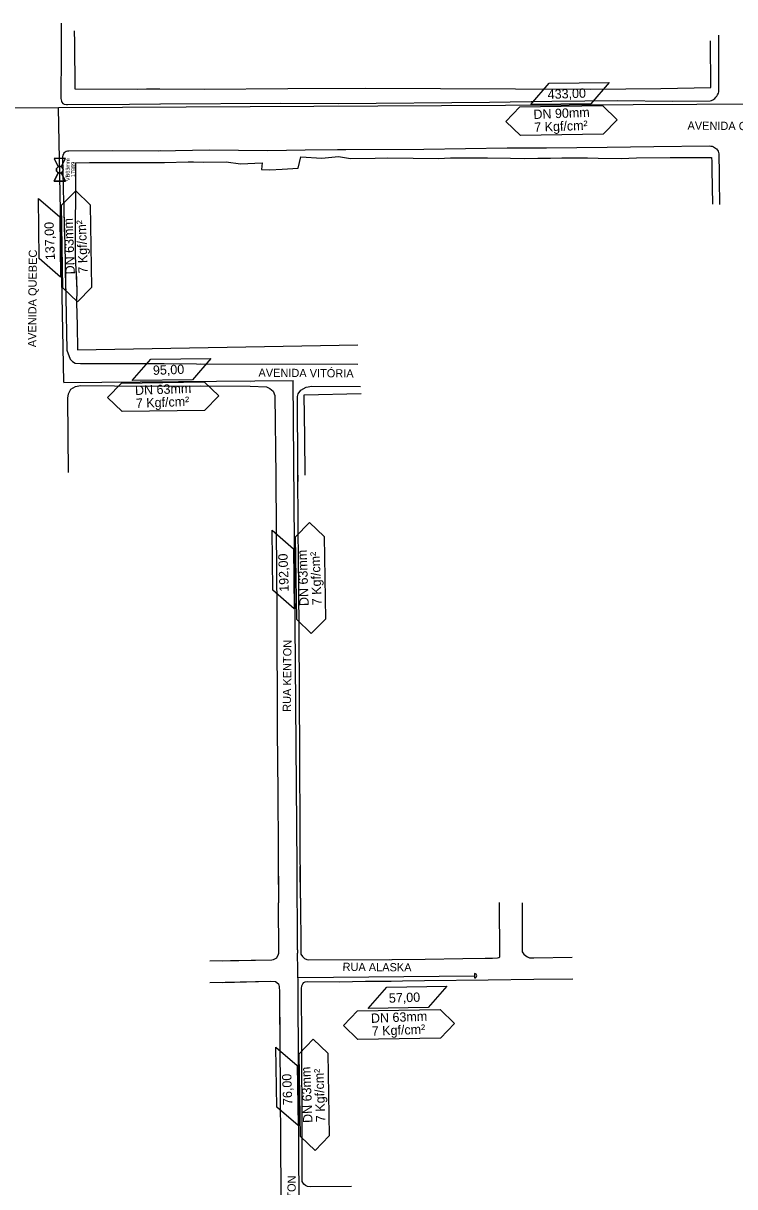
# Model space of a CAD drawing. Extents: x 325899 to 364828, y 7568995 to 7592502.
# Drawn here: x 357435 to 358234, y 7573672 to 7574979 of the extents above; entities that cross this region are included whole.
import ezdxf

# ---------------------------------------------------------------- set-up
doc = ezdxf.new("R2010")
doc.units = 0
for name, color, linetype in [('COTAS', 7, 'Continuous'), ('MEIO_FIO_GUIA', 7, 'Continuous'), ('MURO_DIVISA', 7, 'Continuous'), ('SIMBOLO', 7, 'Continuous'), ('TEXTO', 7, 'Continuous'), ('TUBO_PEAD_GN_63', 7, 'Continuous'), ('TUBO_PEAD_GN_90', 7, 'Continuous'), ('VALVULA_PEAD_63', 7, 'Continuous')]:
    doc.layers.add(name, color=color, linetype=linetype)

# ---------------------------------------------------------------- blocks, each defined once
blk = doc.blocks.new('POINT_DISPLAY')
blk.add_line((0, 0), (0, 0))
blk = doc.blocks.new('VALVULA_PEAD_DN_63_1')
for points in [[(-1.14, 0.57), (-4.25, 2.13), (-4.25, -2.13), (-1.14, -0.57)], [(-1.14, -0.57), (-4.25, -2.13), (-4.25, 2.13), (-1.14, 0.57)], [(1.14, -0.57), (4.25, -2.13), (4.25, 2.13), (1.14, 0.57)], [(1.14, -0.57), (4.25, -2.13), (4.25, 2.13), (1.14, 0.57)]]:
    blk.add_lwpolyline(points)
blk.add_circle((0, 0), 1.28)
for start, end in [(90, 270), (153.4349, 180), (180, 206.5651), (270, 90), (0, 26.5651), (333.4349, 360)]:
    blk.add_arc((0, 0), 1.28, start, end)

msp = doc.modelspace()

# ---------------------------------------------------------------- linework, layer by layer
at = {"layer": 'MEIO_FIO_GUIA'}
for p, q in [((357634.2, 7574596.2), (357810.8, 7574595.9)), ((357634.3, 7574571.2), (357689.9, 7574571.1)), ((357721.3, 7574031.4), (357721.7, 7573990.7)), ((357746.2, 7573995.8), (357746, 7574031.4))]:
    msp.add_line(p, q, dxfattribs=at)
for points in [[(357477.5, 7574978.7), (357477.3, 7574944.4), (357477.2, 7574894.2), (357477.5, 7574892.5), (357477.7, 7574891.2), (357478.2, 7574890), (357479.5, 7574888.7), (357480.7, 7574888), (357483.4, 7574887.5), (357484.6, 7574887.5), (357554.2, 7574888), (357588.4, 7574888.3)], [(357477.5, 7574978.7), (357477.3, 7574944.4), (357477.2, 7574894.2), (357477.5, 7574892.5), (357477.7, 7574891.2), (357478.2, 7574890), (357479.5, 7574888.7), (357480.7, 7574888), (357483.4, 7574887.5), (357484.6, 7574887.5), (357554.2, 7574888), (357588.9, 7574888.3), (357724, 7574888.9), (357789, 7574888.5), (357958.5, 7574889.9), (358028.5, 7574891.2), (358102.8, 7574891.8), (358163.6, 7574891.3), (358206.3, 7574891.6), (358207.9, 7574892), (358209.4, 7574892.7), (358210.7, 7574893.4), (358211.8, 7574894.3), (358212.9, 7574895.5), (358213.9, 7574896.8), (358214.7, 7574898.3), (358215.6, 7574900.2), (358216, 7574901.7), (358216, 7574903), (358216.1, 7574965.2)], [(357480.5, 7574777), (357479.5, 7574828.6), (357479.6, 7574830.5), (357480.3, 7574832.3), (357481.2, 7574833.7), (357481.8, 7574834.2), (357483.1, 7574834.9), (357484.4, 7574835.3), (357486, 7574835.5), (357535.2, 7574835.6), (357587.3, 7574835.5), (357643.5, 7574836.6), (357709.6, 7574835.9), (357751.5, 7574836.4), (357787.9, 7574836.8), (357797, 7574836.9), (357884.8, 7574837.3), (357978.3, 7574838.7), (358022.4, 7574838.9), (358090.8, 7574839.6), (358143.2, 7574840.2), (358205.6, 7574841), (358207.3, 7574840.8), (358208.7, 7574840.5), (358210.2, 7574839.9), (358211.3, 7574839.2), (358212.5, 7574838.5), (358213.5, 7574837.7), (358214.6, 7574836.3), (358215.4, 7574835), (358215.8, 7574833.7), (358216.2, 7574832.2), (358216.3, 7574830.8), (358216.5, 7574810.2), (358216.5, 7574802.9), (358216.9, 7574775.2)], [(357480.5, 7574777), (357479.5, 7574828.6), (357479.6, 7574830.5), (357480.3, 7574832.3), (357481.2, 7574833.7), (357481.8, 7574834.2), (357483.1, 7574834.9), (357484.4, 7574835.3), (357486, 7574835.5), (357535.2, 7574835.6), (357587.3, 7574835.5), (357589.2, 7574835.6)], [(357480.5, 7574777), (357480.6, 7574767.5), (357481.4, 7574729.4), (357482.6, 7574670.5), (357483.7, 7574611.3), (357487.4, 7574601.4), (357490.3, 7574598.6), (357493.2, 7574597), (357499, 7574596.5), (357558.6, 7574596.5), (357593.2, 7574596.4)], [(357480.5, 7574777), (357480.6, 7574767.5), (357481.2, 7574736.2)], [(357482, 7574699.7), (357482.6, 7574670.5), (357483.7, 7574611.3), (357487.4, 7574601.4), (357490.3, 7574598.6), (357493.2, 7574597), (357499, 7574596.5), (357558.6, 7574596.5), (357629.4, 7574596.2), (357810.8, 7574595.9)], [(357485.6, 7574473.9), (357485, 7574557.7), (357485.5, 7574562.4), (357488.3, 7574567.5), (357493.5, 7574570.6), (357499, 7574571.6), (357575.7, 7574571.1), (357593.6, 7574571.2)], [(357485.6, 7574473.9), (357485, 7574557.7), (357485.5, 7574562.4), (357488.3, 7574567.5), (357493.5, 7574570.6), (357499, 7574571.6), (357575.7, 7574571.1), (357622.1, 7574571.2), (357689.9, 7574571.1)], [(357689.9, 7574571.1), (357708.2, 7574570.3), (357711.9, 7574568.5), (357715.6, 7574565.2), (357717.5, 7574560.6), (357718.5, 7574469.7), (357718.8, 7574409.6), (357719.5, 7574318.5), (357720.2, 7574184.1), (357720.7, 7574114.5), (357721.1, 7574051), (357721.7, 7573990.7)], [(357743.5, 7574464), (357743.4, 7574478.8), (357742.9, 7574559.3), (357743.7, 7574562.5), (357746.7, 7574566.6), (357752.8, 7574569.7), (357759, 7574570.9), (357813.5, 7574570.8)], [(357746.2, 7573995.8), (357745.9, 7574071), (357745.5, 7574155.7), (357744.7, 7574295.7), (357744.3, 7574344), (357743.6, 7574409.8), (357743.4, 7574478.8), (357742.9, 7574559.3), (357743.7, 7574562.5), (357746.7, 7574566.6), (357752.8, 7574569.7), (357759, 7574570.9), (357813.5, 7574570.8)], [(357644.4, 7573925.2), (357714, 7573926.5), (357716.1, 7573926.9), (357716.1, 7573926.9), (357719.7, 7573928.6), (357721.6, 7573932.8), (357721.8, 7573933.9), (357721.7, 7573990.7)], [(357644.4, 7573925.2), (357714, 7573926.5), (357716.1, 7573926.9), (357716.1, 7573926.9), (357719.7, 7573928.6), (357721.6, 7573932.8), (357721.8, 7573933.9), (357721.7, 7573990.7)], [(357658.5, 7573925.5), (357714, 7573926.5), (357716.1, 7573926.9), (357716.1, 7573926.9), (357719.7, 7573928.6), (357721.6, 7573932.8), (357721.8, 7573933.9), (357721.7, 7573990.7)], [(357658.5, 7573925.5), (357714, 7573926.5), (357716.1, 7573926.9), (357716.1, 7573926.9), (357719.7, 7573928.6), (357721.6, 7573932.8), (357721.8, 7573933.9), (357721.7, 7573990.7)], [(357746.2, 7573995.8), (357746.5, 7573935.9), (357746.7, 7573932.8), (357748.4, 7573930.2), (357750.9, 7573928.1), (357753.2, 7573926.9), (357755, 7573926.6), (357846.5, 7573927)], [(357746.2, 7573995.8), (357746.5, 7573935.9), (357746.7, 7573932.8), (357748.4, 7573930.2), (357750.9, 7573928.1), (357753.2, 7573926.9), (357755, 7573926.6), (357849.2, 7573927), (357886.3, 7573927.2), (357928.5, 7573928.1), (357953.8, 7573928.2), (357961.8, 7573928.5), (357967.7, 7573928.6), (357969.1, 7573929.1), (357970.1, 7573930), (357970.2, 7573931.5), (357969.8, 7573990.9)], [(357746.2, 7573995.8), (357746.5, 7573935.9), (357746.7, 7573932.8), (357748.4, 7573930.2), (357750.9, 7573928.1), (357753.2, 7573926.9), (357755, 7573926.6), (357846.5, 7573927)], [(357746.2, 7573995.8), (357746.5, 7573935.9), (357746.7, 7573932.8), (357748.4, 7573930.2), (357750.9, 7573928.1), (357753.2, 7573926.9), (357755, 7573926.6), (357848, 7573927)], [(357995.1, 7573990.7), (357995.2, 7573937.5), (357995.4, 7573935.5), (357996.1, 7573934.2), (357997.2, 7573932.8), (357999.2, 7573930.9), (358001.1, 7573929.7), (358003.6, 7573928.7), (358008.5, 7573928.9), (358051.5, 7573929.4)], [(357644.6, 7573900.9), (357712.6, 7573902.4), (357718.1, 7573902.2), (357721.4, 7573899.6), (357722.2, 7573896.7), (357722.8, 7573890.6), (357723.2, 7573821.4)], [(357644.6, 7573900.9), (357712.6, 7573902.4), (357718.1, 7573902.2), (357721.4, 7573899.6), (357722.2, 7573896.7), (357722.8, 7573890.6), (357724.4, 7573608.2), (357725.4, 7573408.3), (357725.5, 7573389.6), (357725.4, 7573386.4), (357725, 7573384.3), (357724.2, 7573382.9), (357722.4, 7573381.4), (357720.8, 7573380.5), (357718.9, 7573379.9), (357716.7, 7573379.6), (357708.4, 7573379.6), (357687.7, 7573378.7), (357649.4, 7573379.1)], [(357658.5, 7573901.1), (357712.6, 7573902.4), (357718.1, 7573902.2), (357721.4, 7573899.6), (357722.2, 7573896.7), (357722.8, 7573890.6), (357723.2, 7573821.4)], [(357658.5, 7573901.1), (357712.6, 7573902.4), (357718.1, 7573902.2), (357721.4, 7573899.6), (357722.2, 7573896.7), (357722.8, 7573890.6), (357723.2, 7573816.3)], [(357747.9, 7573821.4), (357747.7, 7573849.6), (357747.5, 7573877.4), (357747.5, 7573894.4), (357747.9, 7573897.4), (357749, 7573899.7), (357750.1, 7573900.9), (357751.5, 7573901.6), (357754.5, 7573902.3), (357790, 7573901.9), (357819.3, 7573902.5), (357861, 7573902.8), (357885.7, 7573903.1), (357957, 7573904), (358008.2, 7573904.6), (358052.1, 7573905.1)], [(357747.9, 7573821.4), (357747.7, 7573849.6), (357747.5, 7573877.4), (357747.5, 7573894.4), (357747.9, 7573897.4), (357749, 7573899.7), (357750.1, 7573900.9), (357751.5, 7573901.6), (357754.5, 7573902.3), (357790, 7573901.9), (357819.3, 7573902.5), (357846.3, 7573902.7)], [(357803.7, 7573672), (357757, 7573671.6), (357754.1, 7573671.9), (357751.7, 7573672.9), (357750.1, 7573674.6), (357748.2, 7573677.5), (357748.3, 7573680.7), (357748.2, 7573717.1), (357747.7, 7573849.6), (357747.5, 7573877.4), (357747.5, 7573894.4), (357747.9, 7573897.4), (357749, 7573899.7), (357750.1, 7573900.9), (357751.5, 7573901.6), (357754.5, 7573902.3), (357790, 7573901.9), (357819.3, 7573902.5), (357846.3, 7573902.7)], [(357747.9, 7573816.4), (357747.7, 7573849.6), (357747.5, 7573877.4), (357747.5, 7573894.4), (357747.9, 7573897.4), (357749, 7573899.7), (357750.1, 7573900.9), (357751.5, 7573901.6), (357754.5, 7573902.3), (357790, 7573901.9), (357819.3, 7573902.5), (357848.1, 7573902.7)]]:
    msp.add_lwpolyline(points, dxfattribs=at)
at = {"layer": 'MURO_DIVISA'}
for points in [[(357492.2, 7574970.1), (357492.3, 7574957.2), (357492.8, 7574904.9), (357562.9, 7574904.8), (357573.4, 7574904.9), (357588.1, 7574904.9)], [(357492.2, 7574970.1), (357492.3, 7574957.2), (357492.8, 7574904.9), (357562.9, 7574904.8), (357573.4, 7574904.9), (357638.2, 7574904.7), (357731.9, 7574905.3), (357818.8, 7574905.9), (358072.4, 7574904.6), (358150.9, 7574905.4), (358207.1, 7574906.6), (358206.9, 7574959.1)], [(357493.6, 7574821.8), (357493.6, 7574821.8), (357493.6, 7574821.8), (357509.4, 7574822.1), (357536.5, 7574822.1), (357577.7, 7574822.2), (357593.6, 7574822.2), (357620, 7574822.9), (357626.2, 7574823), (357636.8, 7574822.6), (357662.6, 7574823.1), (357678.8, 7574820.8), (357703.1, 7574821.9), (357702.6, 7574814.6), (357712, 7574814.1), (357725.6, 7574814.7), (357743.8, 7574815.9), (357746.6, 7574828.7), (357770.4, 7574827.2), (357789, 7574829.2), (357802.4, 7574826.7), (357830.1, 7574827.3), (357844.3, 7574827.5), (357901.2, 7574826.7), (357914.9, 7574827.4), (357940.5, 7574827.4), (357956.4, 7574827.7), (357982, 7574827.2), (357997.5, 7574826.9), (358012.9, 7574827.2), (358027, 7574827.3), (358039.7, 7574827.5), (358068.6, 7574827.5), (358080.6, 7574827.3), (358106.3, 7574826.9), (358123.6, 7574827.4), (358161.6, 7574827.9), (358208, 7574827.9), (358208.1, 7574823.3), (358208.2, 7574813.9), (358209, 7574775.3)], [(357493.6, 7574821.8), (357493.1, 7574716.8), (357494, 7574702.2), (357495.1, 7574678.8), (357494.7, 7574665.1), (357495.1, 7574652), (357495.3, 7574639.7), (357495.8, 7574611.7), (357810.7, 7574617.4)], [(357493.6, 7574821.8), (357493.6, 7574821.8), (357493.6, 7574821.8), (357509.4, 7574822.1), (357536.5, 7574822.1), (357577.7, 7574822.2), (357589.5, 7574822.2)], [(357494.2, 7574699.8), (357495.1, 7574678.8), (357494.7, 7574665.1), (357495.1, 7574652), (357495.3, 7574639.7), (357495.8, 7574611.7)], [(357751.6, 7574470.9), (357751.2, 7574514.1), (357750.3, 7574561.4), (357814.3, 7574562.8)], [(357751.6, 7574470.9), (357751.2, 7574514.1), (357750.3, 7574561.4), (357814.3, 7574562.8)]]:
    msp.add_lwpolyline(points, dxfattribs=at)
at = {"layer": 'SIMBOLO'}
for points in [[(358072.3, 7574888.3), (358004.9, 7574887.4), (358025.6, 7574911.4), (358093.1, 7574912.3)], [(357475.8, 7574761.1), (357476.7, 7574693.6), (357452.7, 7574714.3), (357451.8, 7574781.8)], [(357624.8, 7574578.2), (357557.3, 7574577.3), (357578.1, 7574601.2), (357645.6, 7574602.1)], [(357738.4, 7574388.4), (357739.3, 7574320.9), (357715.3, 7574341.7), (357714.4, 7574409.2)], [(357889.8, 7573872.8), (357822.3, 7573871.9), (357843.1, 7573895.9), (357910.6, 7573896.8)], [(357742.6, 7573807.7), (357743.5, 7573740.2), (357719.5, 7573761), (357718.6, 7573828.5)]]:
    msp.add_lwpolyline(points, close=True, dxfattribs=at)
for points in [[(357977, 7574868.4), (357992.8, 7574884.7), (358085.6, 7574886.2), (358101.9, 7574870.3), (358086.1, 7574854), (357993.3, 7574852.5), (357977, 7574868.4)], [(357495.7, 7574665.7), (357479.4, 7574681.5), (357477.9, 7574774.3), (357493.8, 7574790.6), (357510.1, 7574774.8), (357511.5, 7574682), (357495.7, 7574665.7)], [(357529.5, 7574558.2), (357545.3, 7574574.5), (357638.1, 7574576), (357654.4, 7574560.2), (357638.6, 7574543.8), (357545.8, 7574542.4), (357529.5, 7574558.2)], [(357758.4, 7574293.1), (357742, 7574308.9), (357740.6, 7574401.7), (357756.4, 7574418), (357772.7, 7574402.2), (357774.2, 7574309.4), (357758.4, 7574293.1)], [(357794.5, 7573852.9), (357810.3, 7573869.2), (357903.1, 7573870.7), (357919.4, 7573854.8), (357903.6, 7573838.5), (357810.8, 7573837), (357794.5, 7573852.9)], [(357762.6, 7573712.4), (357746.2, 7573728.2), (357744.8, 7573821), (357760.6, 7573837.3), (357776.9, 7573821.5), (357778.4, 7573728.7), (357762.6, 7573712.4)]]:
    msp.add_lwpolyline(points, dxfattribs=at)
at = {"layer": 'TUBO_PEAD_GN_63'}
for p, q in [((357474.6, 7574883.7), (356691.2, 7574879.5)), ((357480.5, 7574575.8), (357474.6, 7574883.7)), ((357480, 7574575.3), (357738.1, 7574577.4)), ((357742.4, 7574031.4), (357738.1, 7574577.4)), ((357743, 7573937.7), (357742.4, 7574031.4)), ((357743.6, 7573896.4), (357743, 7573934)), ((357941.7, 7573911), (357941.7, 7573906.1)), ((357743.5, 7573906.5), (357941.7, 7573908.6)), ((357746.5, 7573290.9), (357743.7, 7573892.3))]:
    msp.add_line(p, q, dxfattribs=at)
for centre, radius, start, end in [((358093, 7573939.7), 350, 180.3298, 180.9349), ((357941.7, 7573908.6), 2.44, 269.8591, 89.8591), ((357393.7, 7573890.7), 350, 0.2706, 0.9349)]:
    msp.add_arc(centre, radius, start, end, dxfattribs=at)
at = {"layer": 'TUBO_PEAD_GN_90'}
msp.add_line((359565.1, 7574894.8), (357474.6, 7574883.7), dxfattribs=at)

# ---------------------------------------------------------------- block references
at = {"layer": 'COTAS', "xscale": 3.500000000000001, "yscale": 3.5000000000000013, "rotation": -142.89062872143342}
for p in [(357479.6, 7574620.8), (357690.5, 7574575.4)]:
    msp.add_blockref('POINT_DISPLAY', p, dxfattribs=at)
at = {"layer": 'VALVULA_PEAD_63', "xscale": 3, "yscale": 3, "rotation": 90}
msp.add_blockref('VALVULA_PEAD_DN_63_1', (357475.9, 7574814.1), dxfattribs=at)

# ---------------------------------------------------------------- texts
at = {"layer": 'TEXTO'}
for s, height, rotation, p in [('433,00', 10.5, 2.0817, (358024.1, 7574893.6)), ('DN 90mm', 10.5, 2.2907, (358008.1, 7574871.1)), ('7 Kgf/cm²', 10.5, 2.2907, (358009, 7574856.6)), ('AVENIDA CANADÁ', 9.221, 359.5098, (358180.9, 7574859.2)), ('137,00', 10.5, 92.0817, (357470.5, 7574712.8)), ('DN 63mm', 10.5, 92.2907, (357492.9, 7574696.8)), ('7 Kgf/cm²', 10.5, 92.2907, (357507.5, 7574697.7)), ('AVENIDA QUEBEC', 9.221, 89.5098, (357449.3, 7574614.7)), ('95,00', 10.5, 2.0817, (357580.7, 7574583.6)), ('AVENIDA VITÓRIA', 9.221, 359.5098, (357699, 7574581.6)), ('DN 63mm', 10.5, 2.2907, (357560.6, 7574561)), ('7 Kgf/cm²', 10.5, 2.2907, (357561.5, 7574546.5)), ('192,00', 10.5, 92.0817, (357733.2, 7574340.2)), ('DN 63mm', 10.5, 92.2907, (357755.6, 7574324.2)), ('7 Kgf/cm²', 10.5, 92.2907, (357770.1, 7574325.1)), ('RUA KENTON', 9.22, 89.5098, (357735.5, 7574205.1)), ('RUA ALASKA', 9.22, 359.5098, (357793.5, 7573914.1)), ('57,00', 10.5, 2.0817, (357845.7, 7573878.2)), ('DN 63mm', 10.5, 2.2907, (357825.6, 7573855.6)), ('7 Kgf/cm²', 10.5, 2.2907, (357826.5, 7573841.1)), ('DN 63mm', 10.5, 92.2907, (357759.8, 7573743.5)), ('76,00', 10.5, 92.0817, (357737.2, 7573763.6)), ('7 Kgf/cm²', 10.5, 92.2907, (357774.3, 7573744.4)), ('RUA KENTON', 9.22, 89.5098, (357740.3, 7573603.3))]:
    msp.add_text(s, height=height, rotation=rotation, dxfattribs=at).set_placement(p)
at = {"layer": 'VALVULA_PEAD_63'}
for s, p in [('VB63mm', (357487.1, 7574801.4)), ('17989', (357493.1, 7574805.8))]:
    msp.add_text(s, height=4.5, rotation=90, dxfattribs=at).set_placement(p)

doc.saveas('drawing.dxf')
